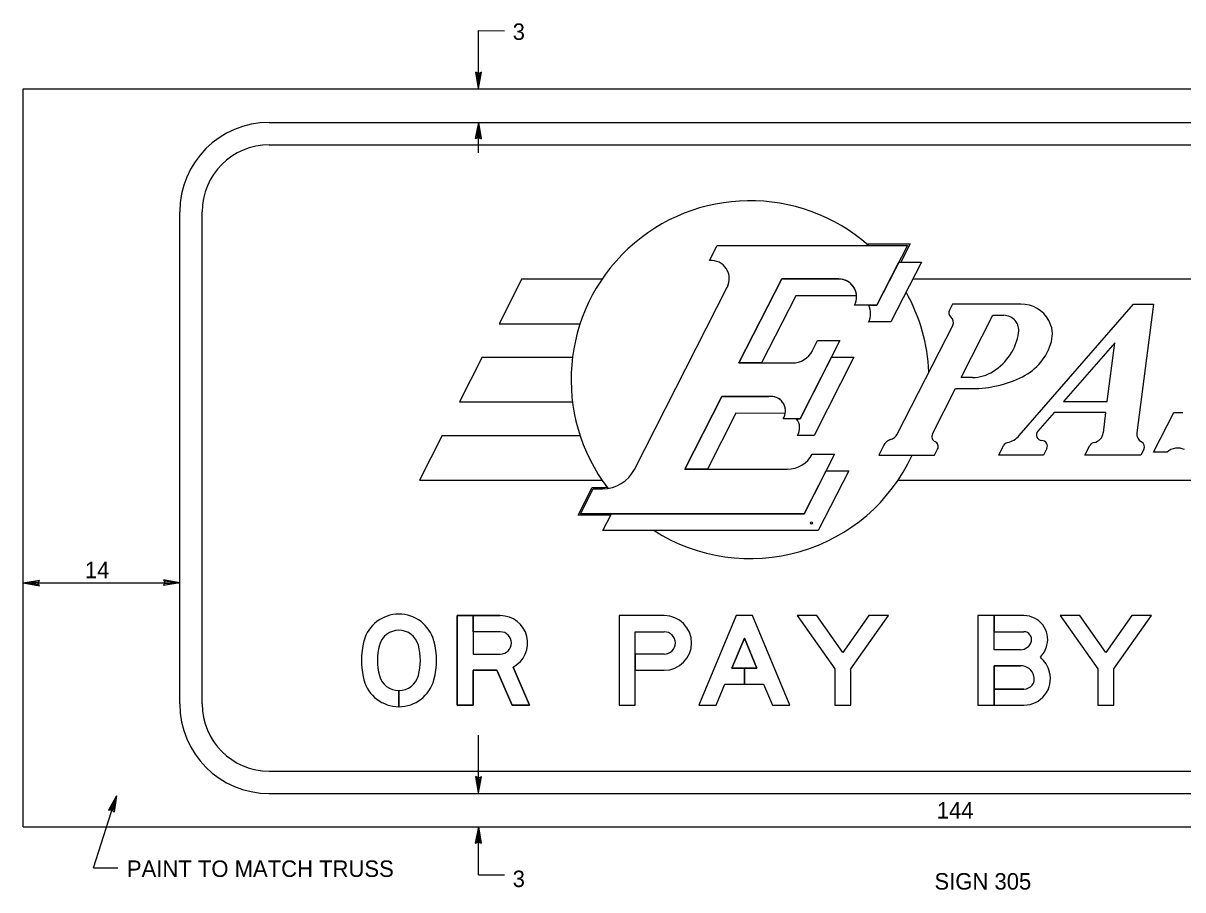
# Model space of a CAD drawing. Extents: x 60714 to 61340, y 9180 to 9758.
# Drawn here: x 60755.6 to 60952.6, y 9610.6 to 9757.9 of the extents above; entities that cross this region are included whole.
import ezdxf

# ---------------------------------------------------------------- set-up
doc = ezdxf.new("R2010")
doc.units = 0
for name, color, linetype in [('1', 7, 'Continuous'), ('2', 7, 'Continuous'), ('52', 7, 'Continuous'), ('GSBWFill', 7, 'Continuous'), ('SignPanel', 7, 'Continuous')]:
    doc.layers.add(name, color=color, linetype=linetype)

msp = doc.modelspace()

# ---------------------------------------------------------------- linework, layer by layer
at = {"layer": '1'}
for p, q in [((60832.94, 9756.59), (60837.35, 9756.56)), ((60832.94, 9746.7), (60832.94, 9756.59)), ((60832.94, 9735.8), (60832.94, 9741)), ((60755.58, 9662.78), (60782.18, 9662.78)), ((60832.94, 9627), (60832.94, 9636.89)), ((60767.53, 9614.37), (60771.44, 9626.61)), ((60832.94, 9613.18), (60832.94, 9621.3)), ((60767.53, 9614.37), (60771.64, 9614.34)), ((60832.94, 9613.18), (60837.35, 9613.16))]:
    msp.add_line(p, q, dxfattribs=at)
msp.add_circle((60889.52, 9672.94), 0.19, dxfattribs=at)
at = {"layer": '2'}
for p, q in [((60755.58, 9621.3), (60755.58, 9746.7)), ((60755.58, 9746.7), (61082.38, 9746.7)), ((60755.58, 9621.3), (61082.38, 9621.3))]:
    msp.add_line(p, q, dxfattribs=at)
at = {"layer": '52'}
for p, q in [((60832.93, 9746.77), (60832.49, 9749.55)), ((60832.97, 9749.33), (60832.49, 9749.55)), ((60832.93, 9746.77), (60832.74, 9749.43)), ((60832.93, 9746.77), (60833.46, 9749.53)), ((60832.93, 9746.77), (60833.2, 9749.43)), ((60833.46, 9749.53), (60832.97, 9749.33)), ((60832.94, 9741), (60832.4, 9738.24)), ((60832.94, 9741), (60832.66, 9738.34)), ((60832.94, 9741), (60833.38, 9738.22)), ((60832.94, 9741), (60833.13, 9738.34)), ((60832.4, 9738.24), (60832.9, 9738.44)), ((60832.9, 9738.44), (60833.38, 9738.22)), ((60755.58, 9662.78), (60758.36, 9663.22)), ((60755.58, 9662.78), (60758.24, 9662.96)), ((60755.58, 9662.78), (60758.34, 9662.24)), ((60755.58, 9662.78), (60758.24, 9662.5)), ((60758.14, 9662.73), (60758.36, 9663.22)), ((60758.34, 9662.24), (60758.14, 9662.73)), ((60779.63, 9662.82), (60779.41, 9662.34)), ((60782.18, 9662.78), (60779.41, 9662.34)), ((60782.18, 9662.78), (60779.42, 9663.31)), ((60779.42, 9663.31), (60779.63, 9662.82)), ((60782.18, 9662.78), (60779.52, 9662.59)), ((60782.18, 9662.78), (60779.53, 9663.06)), ((60832.93, 9627.07), (60832.49, 9629.85)), ((60832.97, 9629.63), (60832.49, 9629.85)), ((60832.93, 9627.07), (60832.74, 9629.73)), ((60832.93, 9627.07), (60833.46, 9629.83)), ((60832.93, 9627.07), (60833.2, 9629.73)), ((60833.46, 9629.83), (60832.97, 9629.63)), ((60771.44, 9626.61), (60770.09, 9624.14)), ((60771.44, 9626.61), (60770.37, 9624.17)), ((60771.44, 9626.61), (60770.81, 9624.02)), ((60771.44, 9626.61), (60771.02, 9623.83)), ((60770.09, 9624.14), (60770.62, 9624.19)), ((60770.62, 9624.19), (60771.02, 9623.83)), ((60832.94, 9621.3), (60832.4, 9618.54)), ((60832.94, 9621.3), (60832.66, 9618.64)), ((60832.94, 9621.3), (60833.38, 9618.52)), ((60832.94, 9621.3), (60833.13, 9618.64)), ((60832.4, 9618.54), (60832.9, 9618.74)), ((60832.9, 9618.74), (60833.38, 9618.52))]:
    msp.add_line(p, q, dxfattribs=at)
at = {"layer": 'GSBWFill'}
for p, q in [((60859.56, 9654.46), (60864.5, 9654.46)), ((60859.56, 9654.46), (60864.5, 9654.46)), ((60859.56, 9654.46), (60864.5, 9654.46)), ((60859.56, 9647.92), (60864.5, 9647.92)), ((60819.42, 9641.73), (60819.42, 9644.46)), ((60819.42, 9644.46), (60819.42, 9641.73)), ((60819.42, 9641.73), (60819.42, 9644.46)), ((60819.42, 9644.46), (60819.42, 9641.73)), ((60917.79, 9641.99), (60925.62, 9641.99))]:
    msp.add_line(p, q, dxfattribs=at)
for points in [[(60836.65, 9657.2), (60829.3, 9657.2), (60829.3, 9641.99), (60832.04, 9641.99), (60832.04, 9647.92), (60836.07, 9647.92), (60838.64, 9641.99), (60841.62, 9641.99), (60838.82, 9648.46)], [(60838.82, 9648.46), (60841.62, 9641.99), (60838.64, 9641.99), (60836.07, 9647.92), (60832.04, 9647.92), (60832.04, 9641.99), (60829.3, 9641.99), (60829.3, 9657.2), (60832.04, 9657.2), (60832.04, 9650.66), (60836.65, 9650.66)], [(60838.82, 9648.46), (60841.62, 9641.99), (60838.64, 9641.99), (60836.07, 9647.92), (60832.04, 9647.92), (60832.04, 9641.99), (60829.3, 9641.99), (60829.3, 9657.2), (60832.04, 9657.2), (60832.04, 9650.66), (60836.65, 9650.66)], [(60832.04, 9654.46), (60832.04, 9657.2), (60836.65, 9657.2)], [(60832.04, 9654.46), (60832.04, 9657.2), (60836.65, 9657.2)], [(60864.5, 9657.2), (60856.82, 9657.2), (60856.82, 9641.99), (60859.56, 9641.99), (60859.56, 9647.92)], [(60864.5, 9657.2), (60856.82, 9657.2), (60856.82, 9641.99), (60859.56, 9641.99), (60859.56, 9654.46)], [(60864.5, 9657.2), (60856.82, 9657.2), (60856.82, 9641.99), (60859.56, 9641.99), (60859.56, 9654.46)], [(60925.62, 9657.2), (60917.79, 9657.2), (60917.79, 9641.99)], [(60925.03, 9651.42), (60920.53, 9651.42), (60920.53, 9657.2), (60917.79, 9657.2), (60917.79, 9641.99), (60920.53, 9641.99)], [(60925.03, 9651.42), (60920.53, 9651.42), (60920.53, 9657.2), (60917.79, 9657.2), (60917.79, 9641.99), (60920.53, 9641.99)], [(60925.62, 9657.2), (60920.53, 9657.2), (60920.53, 9654.46), (60925.62, 9654.46)], [(60925.62, 9657.2), (60920.53, 9657.2), (60920.53, 9654.46), (60925.62, 9654.46)], [(60836.65, 9654.46), (60832.04, 9654.46), (60832.04, 9650.66), (60836.65, 9650.66)], [(60836.65, 9654.46), (60832.04, 9654.46)], [(60836.65, 9654.46), (60832.04, 9654.46)], [(60864.5, 9650.66), (60859.56, 9650.66), (60859.56, 9654.46)], [(60925.03, 9651.42), (60920.53, 9651.42), (60920.53, 9654.46), (60925.62, 9654.46)], [(60864.5, 9650.66), (60859.56, 9650.66), (60859.56, 9647.92), (60864.5, 9647.92)], [(60864.5, 9650.66), (60859.56, 9650.66), (60859.56, 9647.92), (60864.5, 9647.92)], [(60925.03, 9648.68), (60920.53, 9648.68), (60920.53, 9644.73), (60925.62, 9644.73)], [(60920.53, 9641.99), (60920.53, 9648.68), (60925.03, 9648.68)], [(60920.53, 9641.99), (60920.53, 9648.68), (60925.03, 9648.68)], [(60925.62, 9644.73), (60920.53, 9644.73), (60920.53, 9641.99), (60925.62, 9641.99)], [(60925.62, 9644.73), (60920.53, 9644.73), (60920.53, 9641.99), (60925.62, 9641.99)]]:
    msp.add_lwpolyline(points, dxfattribs=at)
for points in [[(60874.82, 9645.57), (60881.39, 9645.57), (60882.89, 9641.99), (60885.86, 9641.99), (60879.48, 9657.2), (60876.74, 9657.2), (60870.35, 9641.99), (60873.32, 9641.99)], [(60880.24, 9648.3), (60878.11, 9648.3), (60878.11, 9645.57), (60881.39, 9645.57), (60882.89, 9641.99), (60885.86, 9641.99), (60879.48, 9657.2), (60876.74, 9657.2), (60870.35, 9641.99), (60873.32, 9641.99), (60874.82, 9645.57), (60878.11, 9645.57), (60878.11, 9648.3), (60875.97, 9648.3), (60878.11, 9653.39)], [(60880.24, 9648.3), (60878.11, 9648.3), (60878.11, 9645.57), (60881.39, 9645.57), (60882.89, 9641.99), (60885.86, 9641.99), (60879.48, 9657.2), (60876.74, 9657.2), (60870.35, 9641.99), (60873.32, 9641.99), (60874.82, 9645.57), (60878.11, 9645.57), (60878.11, 9648.3), (60875.97, 9648.3), (60878.11, 9653.39)], [(60896.2, 9648.15), (60902.59, 9657.2), (60899.24, 9657.2), (60894.83, 9650.96), (60890.43, 9657.2), (60887.08, 9657.2), (60893.46, 9648.15), (60893.46, 9641.99), (60896.2, 9641.99)], [(60896.2, 9648.15), (60902.59, 9657.2), (60899.24, 9657.2), (60894.83, 9650.96), (60890.43, 9657.2), (60887.08, 9657.2), (60893.46, 9648.15), (60893.46, 9641.99), (60896.2, 9641.99)], [(60896.2, 9648.15), (60902.59, 9657.2), (60899.24, 9657.2), (60894.83, 9650.96), (60890.43, 9657.2), (60887.08, 9657.2), (60893.46, 9648.15), (60893.46, 9641.99), (60896.2, 9641.99)], [(60940.9, 9648.15), (60947.28, 9657.2), (60943.93, 9657.2), (60939.53, 9650.96), (60935.13, 9657.2), (60931.78, 9657.2), (60938.16, 9648.15), (60938.16, 9641.99), (60940.9, 9641.99)], [(60940.9, 9648.15), (60947.28, 9657.2), (60943.93, 9657.2), (60939.53, 9650.96), (60935.13, 9657.2), (60931.78, 9657.2), (60938.16, 9648.15), (60938.16, 9641.99), (60940.9, 9641.99)], [(60940.9, 9648.15), (60947.28, 9657.2), (60943.93, 9657.2), (60939.53, 9650.96), (60935.13, 9657.2), (60931.78, 9657.2), (60938.16, 9648.15), (60938.16, 9641.99), (60940.9, 9641.99)], [(60880.24, 9648.3), (60878.11, 9653.39), (60875.97, 9648.3)]]:
    msp.add_lwpolyline(points, close=True, dxfattribs=at)
for centre, radius, start, end in [((60819.42, 9651.3), 6.16, 14.9618, 165.0382), ((60819.42, 9651.3), 6.16, 14.9618, 165.0382), ((60819.42, 9651.3), 6.16, 14.9618, 165.0382), ((60836.65, 9652.56), 4.64, 297.837, 90), ((60836.65, 9652.56), 4.64, 297.837, 90), ((60836.65, 9652.56), 4.64, 297.837, 90), ((60925.62, 9653.17), 4.03, 345.5225, 90), ((60925.62, 9653.17), 4.03, 345.5225, 90), ((60925.62, 9653.17), 4.03, 345.5225, 90), ((60819.42, 9651.3), 3.42, 14.9618, 165.0382), ((60819.42, 9651.3), 3.42, 14.9618, 165.0382), ((60819.42, 9651.3), 3.42, 14.9618, 165.0382), ((60836.65, 9652.56), 1.9, 270, 90), ((60836.65, 9652.56), 1.9, 270, 90), ((60836.65, 9652.56), 1.9, 270, 90), ((60925.62, 9653.17), 1.29, 345.5225, 90), ((60925.62, 9653.17), 1.29, 345.5225, 90), ((60925.62, 9653.17), 1.29, 345.5225, 90), ((60825.81, 9649.6), 12.77, 165.0382, 194.9618), ((60825.81, 9649.6), 12.77, 165.0382, 194.9618), ((60825.81, 9649.6), 12.77, 165.0382, 194.9618), ((60825.81, 9649.6), 10.03, 165.0382, 194.9618), ((60825.81, 9649.6), 10.03, 165.0382, 194.9618), ((60825.81, 9649.6), 10.03, 165.0382, 194.9618), ((60813.04, 9649.6), 10.03, 345.0382, 14.9618), ((60813.04, 9649.6), 10.03, 345.0382, 14.9618), ((60813.04, 9649.6), 10.03, 345.0382, 14.9618), ((60813.04, 9649.6), 12.77, 345.0382, 14.9618), ((60813.04, 9649.6), 12.77, 345.0382, 14.9618), ((60813.04, 9649.6), 12.77, 345.0382, 14.9618), ((60925.03, 9653.32), 1.9, 270, 345.5225), ((60925.03, 9653.32), 1.9, 270, 345.5225), ((60925.03, 9653.32), 1.9, 270, 345.5225), ((60925.03, 9653.32), 4.64, 316.7114, 345.5225), ((60925.03, 9653.32), 4.64, 316.7114, 345.5225), ((60925.03, 9653.32), 4.64, 316.7114, 345.5225), ((60925.03, 9646.33), 5.09, 14.4775, 48.4921), ((60925.03, 9646.33), 5.09, 14.4775, 48.4921), ((60925.03, 9646.33), 5.09, 14.4775, 48.4921), ((60925.03, 9646.33), 2.36, 14.4775, 90), ((60925.03, 9646.33), 2.36, 14.4775, 90), ((60925.03, 9646.33), 2.36, 14.4775, 90), ((60819.42, 9647.89), 6.16, 194.9618, 345.0382), ((60819.42, 9647.89), 6.16, 194.9618, 270), ((60819.42, 9647.89), 6.16, 194.9618, 270), ((60819.42, 9647.89), 3.42, 194.9618, 345.0382), ((60819.42, 9647.89), 3.42, 194.9618, 270), ((60819.42, 9647.89), 3.42, 194.9618, 270), ((60819.42, 9647.89), 3.42, 270.0127, 345.0382), ((60819.42, 9647.89), 3.42, 270.0127, 345.0382), ((60819.42, 9647.89), 6.16, 270.0071, 345.0382), ((60819.42, 9647.89), 6.16, 270.0071, 345.0382), ((60925.62, 9646.48), 4.49, 270, 14.4775), ((60925.62, 9646.48), 4.49, 270, 14.4775), ((60925.62, 9646.48), 4.49, 270, 14.4775), ((60925.62, 9646.48), 1.75, 270, 14.4775), ((60925.62, 9646.48), 1.75, 270, 14.4775), ((60925.62, 9646.48), 1.75, 270, 14.4775)]:
    msp.add_arc(centre, radius, start, end, dxfattribs=at)
for major_axis in [(0, 4.64), (0, 4.64), (0, 4.64), (0, 1.9), (0, 1.9), (0, 1.9)]:
    msp.add_ellipse((60864.5, 9652.56), major_axis=major_axis, ratio=0.999994, start_param=3.141593, end_param=6.283185, dxfattribs=at)
at = {"layer": 'SignPanel'}
for p, q in [((60797.38, 9741), (61040.59, 9741)), ((60797.38, 9737.2), (61040.59, 9737.2)), ((60782.18, 9642.2), (60782.18, 9725.8)), ((60785.98, 9642.2), (60785.98, 9725.8)), ((60872.21, 9717.55), (60873.5, 9720.1)), ((60873.5, 9720.1), (60905.8, 9720.1)), ((60898.86, 9720.38), (60906.27, 9720.38)), ((60905.8, 9720.1), (60900.63, 9709.94)), ((60906.27, 9720.38), (60904.67, 9717.25)), ((60900.62, 9709.93), (60904.36, 9717.25)), ((60900.62, 9709.93), (60904.36, 9717.25)), ((60908.19, 9717.25), (60903.02, 9707.09)), ((60908.19, 9717.25), (60903.02, 9707.09)), ((60904.36, 9717.25), (60908.19, 9717.25)), ((60904.36, 9717.25), (60908.19, 9717.25)), ((60840.32, 9714.4), (60836.46, 9706.8)), ((60840.32, 9714.4), (60853.95, 9714.4)), ((60884.45, 9714.4), (60877.19, 9700.15)), ((60877.19, 9700.15), (60884.45, 9714.4)), ((60877.19, 9700.15), (60884.45, 9714.4)), ((60894.14, 9714.4), (60884.45, 9714.4)), ((60884.45, 9714.4), (60894.14, 9714.4)), ((60884.45, 9714.4), (60894.14, 9714.4)), ((60906.74, 9714.4), (61015.12, 9714.4)), ((60859.44, 9682.05), (60875.21, 9713)), ((60886.84, 9711.55), (60881.03, 9700.15)), ((60886.84, 9711.55), (60881.03, 9700.15)), ((60897.17, 9711.55), (60886.84, 9711.55)), ((60897.17, 9711.55), (60886.84, 9711.55)), ((60900.63, 9709.94), (60896.83, 9709.94)), ((60899.21, 9709.93), (60900.62, 9709.93)), ((60899.21, 9709.93), (60900.62, 9709.93)), ((60913.47, 9710.12), (60912.96, 9709.11)), ((60925.11, 9710.12), (60913.47, 9710.12)), ((60924.82, 9687.81), (60944.22, 9710.12)), ((60944.22, 9710.12), (60947.64, 9710.12)), ((60947.64, 9710.12), (60944.8, 9688.26)), ((60914.96, 9697.68), (60920.34, 9708.22)), ((60920.34, 9708.22), (60922.17, 9708.22)), ((60836.46, 9706.8), (60850.21, 9706.8)), ((60903.02, 9707.09), (60899.22, 9707.09)), ((60903.02, 9707.09), (60899.22, 9707.09)), ((60913.51, 9706.53), (60904.1, 9688.07)), ((60894.35, 9703.95), (60887.57, 9690.65)), ((60889.67, 9702.22), (60890.55, 9703.95)), ((60890.55, 9703.95), (60894.35, 9703.95)), ((60941.04, 9703.57), (60932.36, 9693.59)), ((60939.74, 9693.59), (60941.04, 9703.57)), ((60833.56, 9701.1), (60829.69, 9693.5)), ((60833.56, 9701.1), (60848.92, 9701.1)), ((60877.19, 9700.15), (60886.28, 9700.15)), ((60881.03, 9700.15), (60877.19, 9700.15)), ((60881.03, 9700.15), (60877.19, 9700.15)), ((60887.57, 9690.65), (60892.9, 9701.1)), ((60887.57, 9690.65), (60892.9, 9701.1)), ((60896.73, 9701.1), (60889.96, 9687.8)), ((60896.73, 9701.1), (60889.96, 9687.8)), ((60892.9, 9701.1), (60896.73, 9701.1)), ((60892.9, 9701.1), (60896.73, 9701.1)), ((60916.85, 9697.68), (60914.96, 9697.68)), ((60910.07, 9688.07), (60914, 9695.78)), ((60914, 9695.78), (60916.85, 9695.78)), ((60829.69, 9693.5), (60848.92, 9693.5)), ((60874.29, 9694.45), (60868, 9682.1)), ((60868, 9682.1), (60874.29, 9694.45)), ((60868, 9682.1), (60874.29, 9694.45)), ((60882.63, 9694.45), (60874.29, 9694.45)), ((60874.29, 9694.45), (60882.27, 9694.42)), ((60874.29, 9694.45), (60882.27, 9694.42)), ((60932.36, 9693.59), (60939.74, 9693.59)), ((60876.67, 9691.59), (60871.83, 9682.1)), ((60876.67, 9691.59), (60871.83, 9682.1)), ((60885.06, 9691.56), (60876.67, 9691.59)), ((60885.06, 9691.56), (60876.67, 9691.59)), ((60930.72, 9691.69), (60927.96, 9688.53)), ((60939.55, 9691.69), (60930.72, 9691.69)), ((60939.1, 9688.26), (60939.55, 9691.69)), ((60947.63, 9684.95), (60951.08, 9691.72)), ((60951.08, 9691.72), (60952.6, 9691.72)), ((60887.57, 9690.65), (60884.71, 9690.65)), ((60886.97, 9690.65), (60887.57, 9690.65)), ((60886.97, 9690.65), (60887.57, 9690.65)), ((60826.78, 9687.8), (60822.92, 9680.2)), ((60826.78, 9687.8), (60850.21, 9687.8)), ((60889.96, 9687.8), (60887.11, 9687.8)), ((60889.96, 9687.8), (60887.11, 9687.8)), ((60901.79, 9686.15), (60900.94, 9684.47)), ((60910.44, 9684.47), (60910.95, 9685.49)), ((60921.32, 9684.47), (60922.15, 9686.1)), ((60929.48, 9685.57), (60928.92, 9684.47)), ((60935.98, 9684.47), (60936.82, 9686.12)), ((60945.98, 9685.45), (60945.48, 9684.47)), ((60893.45, 9684.66), (60888.27, 9674.5)), ((60889.65, 9684.66), (60893.45, 9684.66)), ((60900.94, 9684.47), (60910.44, 9684.47)), ((60928.92, 9684.47), (60921.32, 9684.47)), ((60945.48, 9684.47), (60935.98, 9684.47)), ((60949.94, 9684.95), (60947.63, 9684.95)), ((60868, 9682.1), (60885.43, 9682.1)), ((60871.83, 9682.1), (60868, 9682.1)), ((60871.83, 9682.1), (60868, 9682.1)), ((60888.27, 9674.5), (60892, 9681.81)), ((60888.27, 9674.5), (60892, 9681.81)), ((60895.84, 9681.81), (60890.66, 9671.65)), ((60895.84, 9681.81), (60890.66, 9671.65)), ((60892, 9681.81), (60895.84, 9681.81)), ((60892, 9681.81), (60895.84, 9681.81)), ((60822.92, 9680.2), (60853.95, 9680.2)), ((60904.22, 9680.2), (60997.7, 9680.2)), ((60849.87, 9674.25), (60852.28, 9678.98)), ((60850.27, 9674.5), (60852.43, 9678.73)), ((60852.28, 9678.98), (60854.02, 9678.98)), ((60852.43, 9678.73), (60854.02, 9678.73)), ((60855.4, 9674.25), (60849.87, 9674.25)), ((60888.27, 9674.5), (60850.27, 9674.5)), ((60854.07, 9671.65), (60855.52, 9674.5)), ((60854.07, 9671.65), (60855.52, 9674.5)), ((60855.52, 9674.5), (60888.27, 9674.5)), ((60855.52, 9674.5), (60888.27, 9674.5)), ((60890.66, 9671.65), (60854.07, 9671.65)), ((60890.66, 9671.65), (60854.07, 9671.65)), ((60797.38, 9630.8), (61040.59, 9630.8)), ((60797.38, 9627), (61040.59, 9627))]:
    msp.add_line(p, q, dxfattribs=at)
for centre, radius, start, end in [((60797.38, 9725.79), 15.2, 90, 180), ((60797.38, 9725.79), 11.4, 90, 180), ((60879.08, 9697.29), 30.4, 48.5904, 217.4727), ((60872.42, 9714.42), 3.14, 332.9998, 93.8045), ((60894.14, 9711.35), 3.04, 332.2089, 90), ((60894.14, 9711.35), 3.04, 3.5833, 90), ((60894.14, 9711.35), 3.04, 3.5833, 90), ((60879.08, 9697.29), 30.4, 2.4236, 29.2771), ((60896.52, 9708.5), 3.04, 332.2089, 27.9127), ((60896.52, 9708.5), 3.04, 332.2089, 27.9127), ((60913.8, 9708.67), 0.95, 152.9784, 231.1602), ((60925.11, 9704.7), 5.42, 29.4315, 90), ((60912.49, 9707.05), 1.14, 333.0027, 51.1602), ((60922.17, 9705.65), 2.57, 351.076, 90), ((60925.69, 9705.03), 4.75, 344.7074, 29.4315), ((60915.32, 9706.73), 9.5, 302.4206, 351.076), ((60921.11, 9706.28), 9.5, 296.6431, 344.7074), ((60886.28, 9703.94), 3.8, 270, 332.9883), ((60916.85, 9704.32), 6.65, 270, 302.4206), ((60916.85, 9714.77), 19, 270, 296.6431), ((60882.63, 9691.97), 2.47, 350.3502, 98.3344), ((60882.63, 9691.97), 2.47, 350.3502, 98.3344), ((60882.63, 9691.97), 2.47, 327.421, 90), ((60885.03, 9689.12), 2.47, 327.421, 37.9799), ((60885.03, 9689.12), 2.47, 327.421, 37.9799), ((60902.41, 9688.93), 1.9, 286.4317, 332.9959), ((60910.91, 9687.63), 0.95, 152.9884, 244.7832), ((60921.95, 9690.3), 3.8, 282.7162, 318.9966), ((60928.68, 9687.9), 0.95, 138.9824, 268.6869), ((60937.21, 9688.5), 1.9, 279.2397, 352.5632), ((60946.3, 9688.06), 1.52, 172.5884, 241.8673), ((60903.48, 9685.28), 1.9, 106.4317, 152.9742), ((60910.1, 9685.92), 0.95, 333.0239, 64.7832), ((60923, 9685.66), 0.95, 102.7162, 153.0239), ((60928.64, 9686), 0.95, 332.9784, 88.6869), ((60937.67, 9685.69), 0.95, 99.2397, 153.0239), ((60945.14, 9685.88), 0.95, 332.9784, 61.8673), ((60951.75, 9683.01), 2.66, 64.3795, 133.1892), ((60879.08, 9697.29), 30.4, 237.5383, 335.047), ((60885.43, 9686.84), 4.75, 270, 332.5096), ((60854.02, 9684.81), 6.08, 270, 332.9991), ((60854.02, 9684.81), 5.83, 270, 277.5038), ((60797.38, 9642.19), 15.2, 180, 270), ((60797.38, 9642.19), 11.4, 180, 270)]:
    msp.add_arc(centre, radius, start, end, dxfattribs=at)

# ---------------------------------------------------------------- texts
at = {"layer": '1'}
for s, p in [('3', (60838.75, 9755.01)), ('14', (60766.06, 9663.56)), ('144', (60910.8, 9622.72)), ('PAINT TO MATCH TRUSS', (60773.2, 9612.81)), ('3', (60838.75, 9611.09)), ('SIGN 305', (60910.41, 9610.66))]:
    msp.add_text(s, height=2.8, dxfattribs=at).set_placement(p)

doc.saveas('drawing.dxf')
